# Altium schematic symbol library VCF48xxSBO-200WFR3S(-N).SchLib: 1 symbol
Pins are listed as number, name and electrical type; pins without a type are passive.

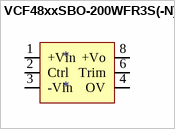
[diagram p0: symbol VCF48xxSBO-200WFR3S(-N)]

## VCF48xxSBO-200WFR3S(-N)
designator *
pins: 1 +Vin, 2 Ctrl, 3 -Vin, 4 OV, 6 Trim, 8 +Vo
